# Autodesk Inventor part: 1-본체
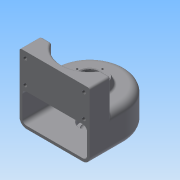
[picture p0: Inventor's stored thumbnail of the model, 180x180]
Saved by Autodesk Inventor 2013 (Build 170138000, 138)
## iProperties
Created: 2015-03
Part Number: 1-본체
Material: 일반
Document SubType Name: Modeling
Designer: Administrator
Density: 1 g/cm^3
Author: Administrator
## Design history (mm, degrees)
sketch "스케치1"
  geometry: L1 (50, 50)-(50, 0); L2 (50, 0)-(-50, 0); L3 (-50, 0)-(-50, 50); A1 r 50 centre (0, 50) between (50, 50) and (-50, 50); 1 further point
  constraints: 6 end point, 2 point on circle, 2 tangent, 2 vertical, 1 centre point, 1 midpoint, 1 perpendicular, 1 vertical alignment
  dimensions: "d1" = 50 radius of A1; "d3" = 50 distance of point (0, 0) A1.centre
extrude "돌출1" new body sketch "스케치1" distance "d4" = 50; taper "d5" = 0 deg
sketch "스케치2"
  geometry: L1 (-50, 0)-(50, 0) reference; L2 (50, 0)-(50, 50) reference; L3 (-50, 50)-(-50, 0) reference; L4 (-50, 30)-(-34.641, 30); L5 (-34.641, 30)-(-34.641, 0); L6 (34.641, 30)-(50, 30); L7 (34.641, 30)-(34.641, 0); L8 (-50, 30)-(-50, 0); L9 (50, 0)-(50, 30); A1 r 50 centre (0, 50) between (50, 50) and (-50, 50) reference; A2 r 40 centre (0, 50) between (-34.641, 30) and (34.641, 30); 1 further point
  constraints: 12 end point, 4 perpendicular, 4 point on line, 2 collinear, 2 point on circle, 1 centre point, 1 coincident
  dimensions: "d6" = 40 radius of A2; "d8" = 30 distance between parallel lines of L1 L4; "d9" = 30 distance between parallel lines of L1 L6
extrude "돌출2" join sketch "스케치2" distance "d10" = 45; taper "d11" = 0 deg
sketch "스케치3"
  geometry: C1 r 25 at (0, 50); A1 r 40 centre (0, 50) between (-34.641, 30) and (34.641, 30) reference; 1 further point
  constraints: 1 centre point, 1 coincident
  dimensions: "d12" = 50 diameter of C1
extrude "돌출3" join sketch "스케치3" distance "d14" = 10; taper "d15" = -20 deg
sketch "스케치4"
  geometry: C1 r 20 at (0, 50); A1 r 50 centre (0, 50) between (50, 50) and (-50, 50) reference; 1 further point
  constraints: 1 centre point, 1 coincident
  dimensions: "d16" = 40 diameter of C1
extrude "돌출4" join sketch "스케치4" distance "d18" = 9; taper "d19" = 0 deg
node "작업 평면1"
sketch "스케치5"
  geometry: L1 (-50, 0)-(-50, 50) reference; L2 (50, 50)-(50, 0) reference; L3 (-46, 0)-(-46, 50); L4 (46, 50)-(46, 0); L5 (-46, 0)-(46, 0); L6 (50, 0)-(-50, 0) reference; A1 r 50 centre (0, 50) between (50, 50) and (-50, 50) reference; A2 r 46 centre (0, 50) between (46, 50) and (-46, 50); 2 further points
  constraints: 6 end point, 2 midpoint, 2 point on circle, 1 centre point, 1 perpendicular, 2 other
  dimensions: "d21" = 4 radial gap between concentric circles of A2 A1
extrude "돌출5" cut sketch "스케치5" distance "d22" = 42; taper "d23" = 0 deg
hole "구멍1" diameter "d26" = 20; stored, may be unused: countersink angle "d30" = 90 deg, drill point angle "d32" = 0 deg; dims "d27" = 6, "d28" = 28, "d29" = 10, "d31" = 8, "d74" = 10, "d75" = 10
hole "구멍2" diameter "d35" = 20; stored, may be unused: countersink angle "d39" = 90 deg, drill point angle "d41" = 0 deg; dims "d33" = 10, "d34" = 10, "d36" = 6, "d37" = 28, "d38" = 8, "d40" = 10
fillet "모깎기1" dims "d42" = 10
fillet "모깎기2" dims "d43" = 6
fillet "모깎기3" dims "d44" = 3
fillet "모깎기4" dims "d45" = 3
node "작업 평면2"
sketch "스케치6"
  geometry: 2 further points
  constraints: 1 vertical alignment, 1 other
  dimensions: "d46" = 25 distance of point (0, 0) point (0, 25)
feature "엠보싱1" sketch "스케치6" dims "d47" = 0.5, "d48" = 0
fillet "모깎기5" dims "d49" = 3
sketch "스케치7"
  geometry: C1 r 14 at (0, 0) reference; C2 r 21.36 at (0, 0) reference; A1 r 18 centre (0, 0) between (0, 18) and (18, 0); 3 further points
  constraints: 4 point on circle, 2 horizontal alignment, 2 vertical alignment, 1 centre point, 1 coincident
  dimensions: "d50" = 36 diameter of A1
hole "구멍3" sketch "스케치7" at (0, 18), (18, 0), (0, -18), (-18, 0) diameter "d52" = 2.459; stored, may be unused: countersink angle "d56" = 90 deg, drill point angle "d58" = 118 deg; dims "d53" = 6, "d54" = 28, "d55" = 8, "d57" = 9
sketch "스케치8"
  geometry: L1 (0, 0)-(80, 0) reference; L2 (-7, 95)-(87, 95) reference; L3 (-1.75, 86)-(81.75, 86); L4 (81.75, 86)-(81.75, 53); L5 (81.75, 53)-(-1.75, 53); L6 (-1.75, 53)-(-1.75, 86); 7 further points
  constraints: 8 end point, 4 coincident, 2 midpoint, 2 parallel, 1 horizontal, 1 perpendicular, 1 vertical alignment
  dimensions: "d59" = 83.5 distance of L3.start L3.end; "d61" = 9 distance between parallel lines of L3 L2; "d62" = 33 distance between parallel lines of L5 L3
hole "구멍4" sketch "스케치8" at (81.75, 86), (81.75, 53), (-1.75, 53), (-1.75, 86) diameter "d63" = 5.134; stored, may be unused: countersink angle "d67" = 90 deg, drill point angle "d69" = 118 deg; dims "d64" = 10, "d65" = 28, "d66" = 8, "d68" = 13
chamfer "모따기1" distance "d70" = 1; stored, may be unused: second distance "d71" = 2, angle "d72" = 45 deg
fillet "모깎기6" dims "d73" = 0.3
fillet "모깎기7" dims "d76" = 3
node "솔리드1"
other parameters: "d20" = -4
